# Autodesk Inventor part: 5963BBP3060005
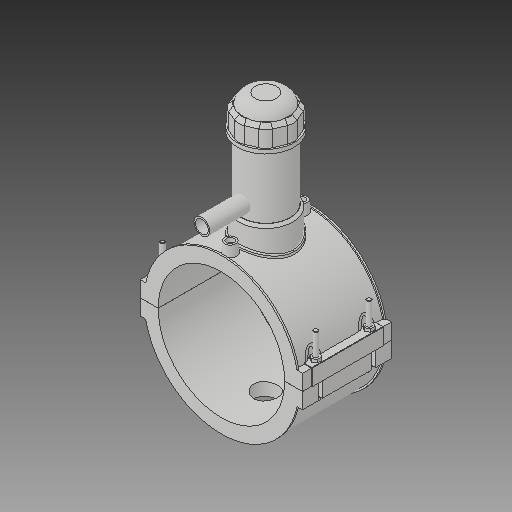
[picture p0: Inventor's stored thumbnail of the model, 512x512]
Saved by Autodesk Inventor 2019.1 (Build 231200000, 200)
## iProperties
Created: 2017-07
Part Number: 5963BBP3060005
Material: Generic
Description: PLASSON TAPPING SADDLE 6''IPS x 1/2''IPS
Document SubType Name: Modeling
Designer: KIM
Density: 1 g/cm^3
Appearance: Default
Author: KIM
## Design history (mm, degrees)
derived "5963BBP_5963BUP.ipt"
feature "Solid1::5963BBP_5963BUP.ipt"
feature "Solid2::5963BBP_5963BUP.ipt"
feature "Solid3::5963BBP_5963BUP.ipt"
tag "TaggingFeature1"
body "Solid1"
body "Solid2"
body "Solid3"
other parameters: "d0" = 168, "d2" = 215.9, "d3" = 42, "d4" = 118.11, "d5" = 0, "d6" = 0.1, "d8" = 0, "d19" = 6, "d20" = 6, "d21" = 70.866, "d23" = 0, "d24" = 35.433, "d26" = 0, "d27" = 3, "d28" = 3, "d29" = 3, "d30" = 56, "d31" = 6, "d32" = 0, "d33" = 0, "d34" = 0.6, "d40" = 104.832, "d41" = 75.6, "d43" = 0, "d45" = 0, "d47" = 171.666, "d70" = 15, "d72" = 0, "d73" = 6, "d75" = 5, "d76" = 0, "d77" = 8.4, "d78" = 114, "d79" = 15, "d80" = 47.244, "d82" = 5 deg, "d84" = 4, "d85" = 14, "d86" = 0, "d87" = 3, "d88" = 0, "d89" = 1, "d90" = 1, "d91" = 94.488, "d92" = 0, "d93" = 0.5, "d94" = 88.42105, "d96" = 205.632, "d97" = 2.3622, "d98" = 0, "d102" = 1.68, "d120" = 140 deg, "d121" = 24.228, "d122" = 20 deg, "d123" = 403.2, "d124" = 120.96, "d126" = 0, "d143" = 173.04, "d145" = 25.84615, "d149" = 2.52, "d150" = 28.43077, "d153" = 118.11, "d154" = 0, "d156" = 100.8, "d157" = 160 deg, "d159" = 6.72, "d161" = 2.52, "d162" = 70.866, "d163" = 0, "d164" = 84, "d167" = 16.8, "d168" = 98.34146, "d170" = 3.2805, "d172" = 0, "d173" = 1, "d175" = 84, "d176" = 20 deg, "d177" = 11.76, "d178" = 33.6, "d180" = 0, "d183" = 13.44, "d184" = 9.408, "d185" = 38.38575, "d186" = 38.38575, "d187" = 100.8, "d188" = 10.08, "d189" = 11.76, "d190" = 0, "d191" = 151.2, "d193" = 6.9984, "d194" = 4.13385, "d195" = 90 deg, "d197" = 0, "d199" = 0, "d200" = 16.8, "d202" = 0, "d203" = 177.038, "d204" = 71.82, "d205" = 52.92, "d206" = 64.26, "d207" = 132.7785, "d208" = 138.08964, "d209" = 164.64534, "d210" = 65.016, "d211" = 75.6, "d212" = 60.48, "d213" = 48.9816, "d216" = 0, "d217" = 16.8, "d218" = 16.8, "d219" = 3.36, "d222" = 168, "d224" = 0, "d225" = 65.024, "d226" = 21.2, "d227" = 16.96, "d228" = 85.09, "d230" = 5.04, "d_" = 168, "B_" = 215.9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
